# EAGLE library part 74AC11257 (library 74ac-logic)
Quadruple 2 to 1 line DATA SELECTOR/MULTIPLEXER, 3-state
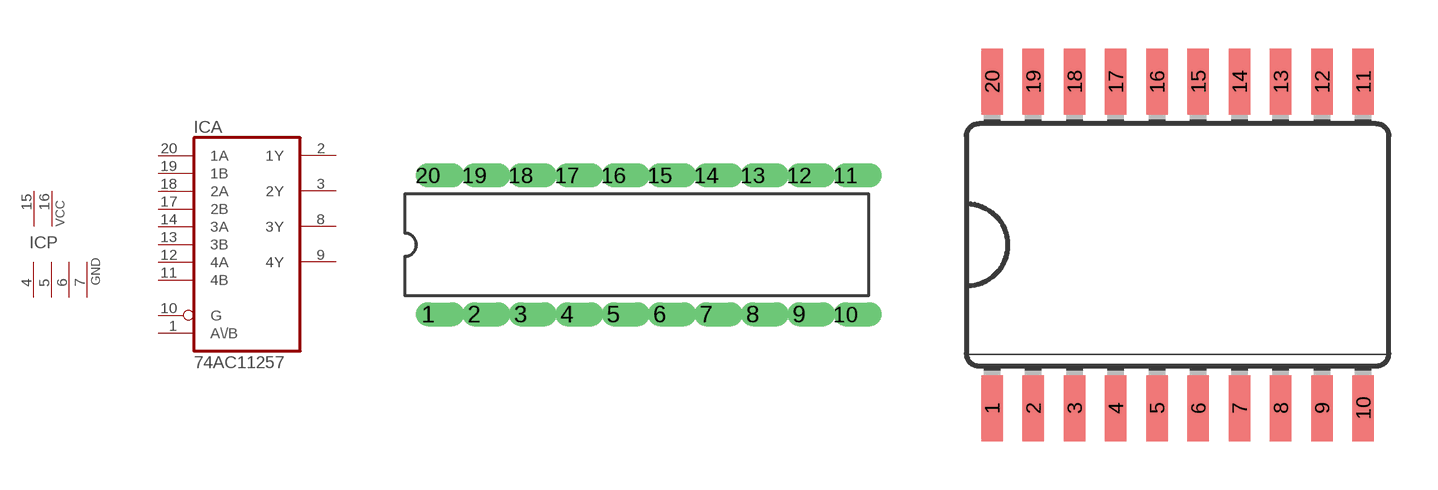
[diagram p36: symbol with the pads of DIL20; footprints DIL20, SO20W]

Designator prefix IC; gates A=7411257 P=2PWR4GND

## 74AC11257  [DIL20]
1  A:A\/B  in
2  A:1Y  hiz
3  A:2Y  hiz
4  P:GND  pwr
5  P:GND  pwr
6  P:GND  pwr
7  P:GND  pwr
8  A:3Y  hiz
9  A:4Y  hiz
10  A:G  in
11  A:4B  in
12  A:4A  in
13  A:3B  in
14  A:3A  in
15  P:VCC  pwr
16  P:VCC  pwr
17  A:2B  in
18  A:2A  in
19  A:1B  in
20  A:1A  in

## 74AC11257D  [SO20W]
Pads as for DIL20

## Footprint DIL20 (pad centres in mm)
Dual In Line
drill 0.813 offset: 1 -11.43,-3.81; 2 -8.89,-3.81; 3 -6.35,-3.81; 4 -3.81,-3.81; 5 -1.27,-3.81; 6 1.27,-3.81; 7 3.81,-3.81; 8 6.35,-3.81; 9 8.89,-3.81; 10 11.43,-3.81; 11 11.43,3.81; 12 8.89,3.81; 13 6.35,3.81; 14 3.81,3.81; 15 1.27,3.81; 16 -1.27,3.81; 17 -3.81,3.81; 18 -6.35,3.81; 19 -8.89,3.81; 20 -11.43,3.81

## Footprint SO20W (pad centres in mm)
Wide Small Outline package 300 mil
smd 0.66 x 2.032: 1 -5.715,-5.029; 2 -4.445,-5.029; 3 -3.175,-5.029; 4 -1.905,-5.029; 5 -0.635,-5.029; 6 0.635,-5.029; 7 1.905,-5.029; 8 3.175,-5.029; 9 4.445,-5.029; 10 5.715,-5.029; 11 5.715,5.029; 12 4.445,5.029; 13 3.175,5.029; 14 1.905,5.029; 15 0.635,5.029; 16 -0.635,5.029; 17 -1.905,5.029; 18 -3.175,5.029; 19 -4.445,5.029; 20 -5.715,5.029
